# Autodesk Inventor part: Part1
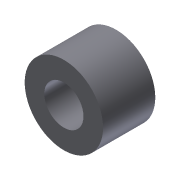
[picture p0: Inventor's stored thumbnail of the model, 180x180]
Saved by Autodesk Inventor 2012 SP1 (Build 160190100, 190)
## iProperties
Created: 2012-04
Part Number: Part1
Material: Steel, Mild
Document SubType Name: Modeling
Designer: dmm70056
Density: 7.86 g/cm^3
Mass: 170.709 g
Surface Area: 62.7051 cm^2
Volume: 21.7187 cm^3
Author: dmm70056
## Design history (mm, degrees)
sketch "Sketch1"
  geometry: C1 r 19.05 at (18.708, 21.031); 1 further point
  constraints: 1 centre point
  dimensions: "d2" = 38.1 diameter of C1
extrude "Extrusion1" new body sketch "Sketch1" distance "d0" = 25.4; taper "d1" = 0 deg
hole "Hole1" diameter "d5" = 19.05; stored, may be unused: countersink angle "d9" = 82 deg, drill point angle "d11" = 118 deg; dims "d6" = 19.05, "d7" = 9.525, "d8" = 6.35, "d10" = 25.4, "d12" = 25.4, "d13" = 25.4
body "Solid1"
